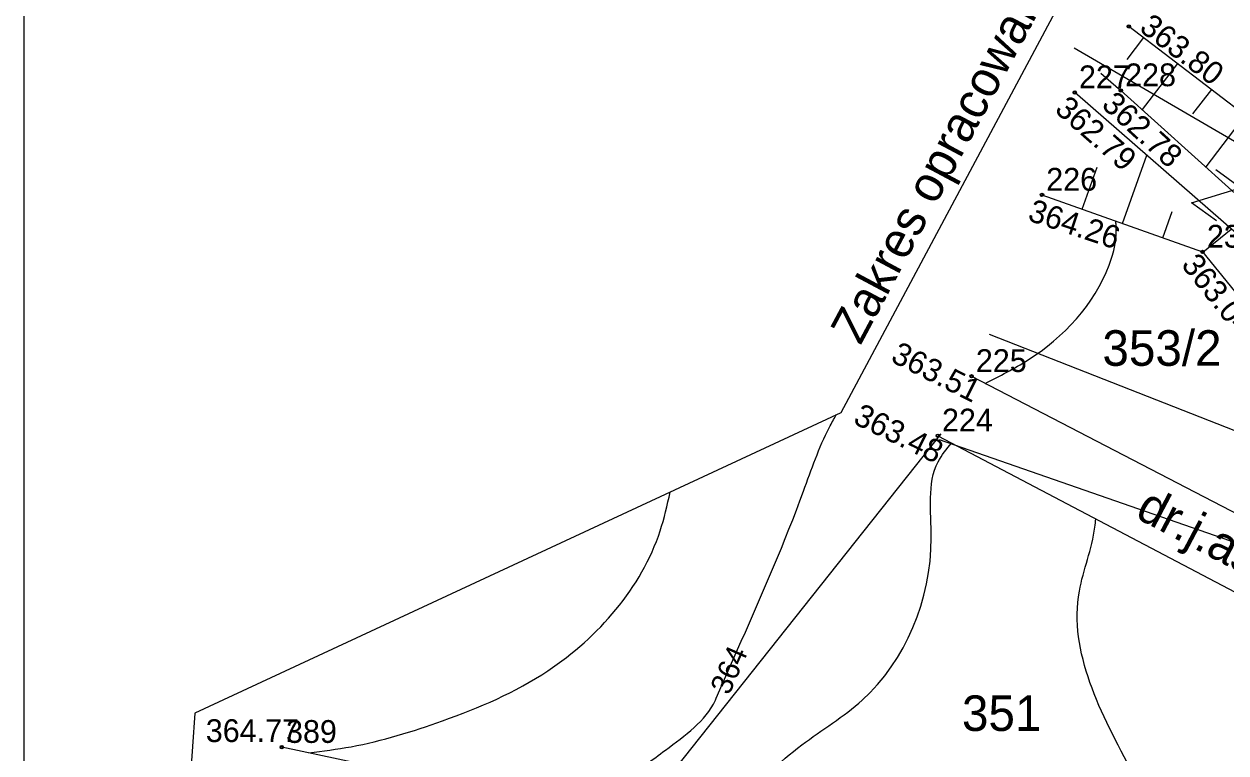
# Model space of a CAD drawing. Extents: x 4635329 to 4651863, y 5356628 to 5367582.
# Drawn here: x 4651671.38 to 4651713.58, y 5357155.39 to 5357181 of the extents above; entities that cross this region are included whole.
import ezdxf

# ---------------------------------------------------------------- set-up
doc = ezdxf.new("R2010")
doc.units = 0
for name, color, linetype in [('Level 1', 7, 'Continuous'), ('Level 13', 7, 'Continuous'), ('Level 2', 7, 'Continuous'), ('Level 20', 7, 'Continuous'), ('Level 21', 7, 'Continuous'), ('Level 4', 7, 'Continuous'), ('Level 44', 7, 'Continuous'), ('Level 45', 7, 'Continuous'), ('Level 46', 7, 'Continuous'), ('Level 47', 7, 'Continuous'), ('Level 48', 7, 'Continuous'), ('Level 5', 7, 'Continuous'), ('Level 50', 7, 'Continuous'), ('Level 53', 7, 'Continuous'), ('Level 6', 7, 'Continuous'), ('Level 63', 7, 'Continuous')]:
    doc.layers.add(name, color=color, linetype=linetype)

msp = doc.modelspace()

# ---------------------------------------------------------------- linework, layer by layer
at = {"layer": 'Level 1'}
for p, q in [((4651710.481, 5357186.845), (4651700.061, 5357167.337)), ((4651700.061, 5357167.337), (4651677.384, 5357156.784)), ((4651677.384, 5357156.784), (4651674.731, 5357120.311))]:
    msp.add_line(p, q, dxfattribs=at)
at = {"layer": 'Level 13'}
msp.add_lwpolyline([(4651671.382, 5357244.835), (4651857.008, 5357244.835), (4651857.008, 5357005.82), (4651671.382, 5357005.82)], close=True, dxfattribs=at)
at = {"layer": 'Level 2'}
msp.add_line((4651703.566, 5357166.6), (4651692.792, 5357153.016), dxfattribs=at)
at = {"layer": 'Level 20'}
for points in [[(4651704.65, 5357168.62), (4651722.86, 5357159.17), (4651726.77, 5357157.8), (4651728.792, 5357158.081), (4651729.9, 5357158.7)], [(4651703.46, 5357166.53), (4651721.83, 5357156.87), (4651725.65, 5357154.91), (4651727.94, 5357152.83), (4651728.67, 5357151.53)]]:
    msp.add_lwpolyline(points, dxfattribs=at)
at = {"layer": 'Level 4'}
for p, q in [((4651730.567, 5357167.111), (4651708.252, 5357180.152)), ((4651727.96, 5357161.166), (4651705.281, 5357170.083)), ((4651726.979, 5357158.218), (4651703.522, 5357166.383))]:
    msp.add_line(p, q, dxfattribs=at)
at = {"layer": 'Level 44'}
for centre in [(4651710.17, 5357180.91), (4651709.89, 5357178.66), (4651708.27, 5357178.59), (4651707.12, 5357174.99), (4651712.76, 5357172.99), (4651704.65, 5357168.62), (4651703.46, 5357166.53), (4651680.43, 5357155.59)]:
    msp.add_circle(centre, 0.04, dxfattribs=at)
at = {"layer": 'Level 46'}
msp.add_line((4651695.684, 5357157.309), (4651696.563, 5357159.309), dxfattribs=at)
for points in [[(4651705.13, 5357168.371), (4651706.63, 5357169.193), (4651709.48, 5357172.528), (4651709.722, 5357173.923), (4651709.709, 5357174.072)], [(4651696.563, 5357159.309), (4651698.748, 5357164.583), (4651699.657, 5357166.827), (4651699.895, 5357167.26)], [(4651693.972, 5357152.424), (4651696.383, 5357153.787), (4651698.687, 5357155.667), (4651700.809, 5357157.244), (4651703.234, 5357162.945), (4651703.477, 5357165.614), (4651703.944, 5357166.275)], [(4651681.378, 5357155.388), (4651682.862, 5357155.607), (4651686.075, 5357156.516), (4651689.774, 5357158.275), (4651693.715, 5357163.188), (4651694.066, 5357164.547)], [(4651710.321, 5357154.652), (4651708.433, 5357161.075), (4651708.978, 5357163.319), (4651709.008, 5357163.613)], [(4651699.387, 5357150.073), (4651701.719, 5357150.572), (4651704.872, 5357149.784), (4651707.903, 5357148.45), (4651710.995, 5357148.025), (4651714.33, 5357147.843), (4651719.06, 5357153.605), (4651719.242, 5357156.395), (4651719.388, 5357158.154)], [(4651685.635, 5357154.482), (4651687.712, 5357154.697), (4651690.501, 5357154.636), (4651692.502, 5357154.636), (4651693.897, 5357155.485), (4651695.655, 5357157.244), (4651695.684, 5357157.309)]]:
    msp.add_spline(points, degree=3, dxfattribs=at)
at = {"layer": 'Level 48'}
for p, q in [((4651710.682, 5357180.519), (4651710.097, 5357179.754)), ((4651711.874, 5357179.609), (4651710.636, 5357177.989)), ((4651713.066, 5357178.698), (4651712.41, 5357177.84)), ((4651714.258, 5357177.788), (4651712.873, 5357175.975)), ((4651709.947, 5357173.987), (4651710.797, 5357176.383)), ((4651708.534, 5357174.489), (4651709.058, 5357175.966)), ((4651711.361, 5357173.486), (4651711.687, 5357174.404)), ((4651712.77, 5357172.978), (4651713.768, 5357173.788))]:
    msp.add_line(p, q, dxfattribs=at)
for points in [[(4651728.68, 5357162.99), (4651720.42, 5357169.27), (4651715.93, 5357176.51), (4651710.17, 5357180.91)], [(4651707.12, 5357174.99), (4651712.76, 5357172.99), (4651716.99, 5357167.781), (4651720.28, 5357162.11), (4651726.9, 5357158.63)], [(4651721.23, 5357139.36), (4651715.28, 5357144.23), (4651708.01, 5357146.33), (4651692.69, 5357152.98), (4651680.43, 5357155.59)]]:
    msp.add_lwpolyline(points, dxfattribs=at)
at = {"layer": 'Level 50'}
for points in [[(4651709.189, 5357179.27), (4651709.89, 5357178.66), (4651715.09, 5357173.98), (4651720.27, 5357166.06), (4651727.89, 5357161.85)], [(4651727.33, 5357160.79), (4651720.89, 5357164.32), (4651719.558, 5357165.632), (4651714.04, 5357173.55), (4651708.27, 5357178.59)]]:
    msp.add_lwpolyline(points, dxfattribs=at)
at = {"layer": 'Level 53'}
for p, q in [((4651714.095, 5357175.241), (4651713.223, 5357175.878)), ((4651712.375, 5357174.715), (4651714.095, 5357175.241)), ((4651713.247, 5357174.078), (4651712.375, 5357174.715))]:
    msp.add_line(p, q, dxfattribs=at)
at = {"layer": 'Level 63'}
for centre in [(4651710.17, 5357180.91), (4651709.89, 5357178.66), (4651708.27, 5357178.59), (4651707.12, 5357174.99), (4651712.76, 5357172.99), (4651704.65, 5357168.62), (4651703.46, 5357166.53), (4651680.43, 5357155.59)]:
    msp.add_circle(centre, 0.06, dxfattribs=at)

# ---------------------------------------------------------------- texts
at = {"layer": 'Level 21'}
msp.add_text('dr.j.asf. ', height=1.25, rotation=332.262, dxfattribs=at).set_placement((4651710.348, 5357163.676))
at = {"layer": 'Level 45'}
for s, rotation, p in [('363.80', 322.7649, (4651710.5, 5357180.777)), ('362.79', 318.6813, (4651707.529, 5357177.938)), ('362.78', 317.4828, (4651709.174, 5357178.105)), ('364.26', 341.6462, (4651706.583, 5357174.105)), ('363.04', 308.461, (4651711.981, 5357172.525)), ('363.51', 333.1803, (4651701.77, 5357169.155)), ('363.48', 333.9169, (4651700.451, 5357166.979))]:
    msp.add_text(s, height=0.8, rotation=rotation, dxfattribs=at).set_placement(p)
msp.add_text('364.77', height=0.8, dxfattribs=at).set_placement((4651677.764, 5357155.77))
at = {"layer": 'Level 47'}
msp.add_text('364', height=0.75, rotation=66.2946, dxfattribs=at).set_placement((4651696.134, 5357157.387))
at = {"layer": 'Level 5'}
for s, p in [('353/2', (4651709.242, 5357168.987)), ('351', (4651704.311, 5357156.159))]:
    msp.add_text(s, height=1.25, dxfattribs=at).set_placement(p)
at = {"layer": 'Level 6'}
msp.add_text('Zakres opracowania', height=1.25, rotation=61.8916, dxfattribs=at).set_placement((4651700.748, 5357169.684))
at = {"layer": 'Level 63'}
for s, p in [('227', (4651708.42, 5357178.74)), ('228', (4651710.04, 5357178.81)), ('226', (4651707.27, 5357175.14)), ('231', (4651712.91, 5357173.14)), ('225', (4651704.8, 5357168.77)), ('224', (4651703.61, 5357166.68)), ('389', (4651680.58, 5357155.74))]:
    msp.add_text(s, height=0.8, dxfattribs=at).set_placement(p)

doc.saveas('drawing.dxf')
